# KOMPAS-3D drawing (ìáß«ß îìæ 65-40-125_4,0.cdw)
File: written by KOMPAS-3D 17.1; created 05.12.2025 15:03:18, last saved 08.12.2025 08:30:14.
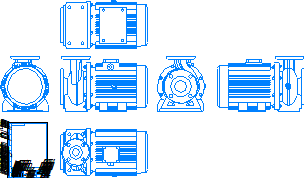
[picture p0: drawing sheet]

Sheet 1: A4, portrait

Title block, sheet 1: name: Насос МНС / 65-40-125_4,0; material: Сталь 10  ГОСТ 1050-88; mass: 119,59; sheets: 1; sheet format: A4; stored path: \\adlc.lan\data\АДЛ_ПКД\3D-модели\ADL production\Насосы ГРАНПАМП\Насосы ГРАНПАМП серии МНС\KOMPAS 2D\Насос МНС 65-40-125_4,0.cdw

Views: Проекционный вид 2, Проекционный вид 3, Проекционный вид 4, Проекционный вид 5, Проекционный вид 6
Referenced files in \\adlc.lan\data\АДЛ_ПКД\3D-модели\ADL production\Насосы ГРАНПАМП\Насосы ГРАНПАМП серии МНС\KOMPAS 3D\: Насос МНС 65-40-125_4,0.m3d
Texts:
  Andrey
  АДЛ
Dimensions and other numbers on the sheet: 1:1; 1; 65-40-125_4,0; 119,59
